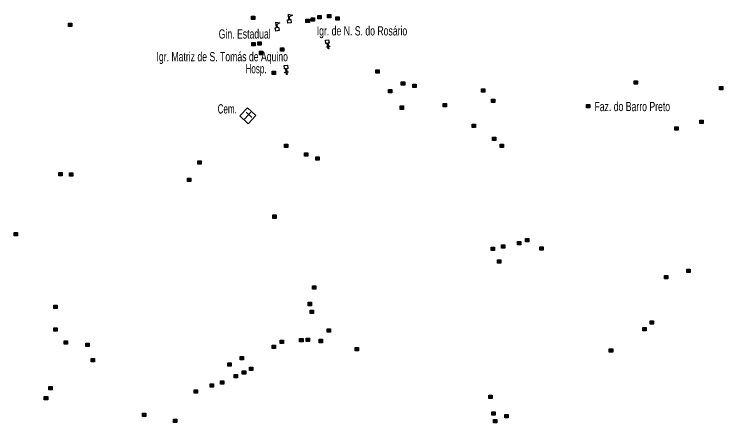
# Model space of a CAD drawing. Extents: x 265.7 to 292.1, y 7676.2 to 7704.2.
# Drawn here: x 279.25 to 285.37, y 7697.19 to 7700.73 of the extents above; entities that cross this region are included whole.
import ezdxf

# ---------------------------------------------------------------- set-up
doc = ezdxf.new("R2010")
doc.units = 0
doc.header["$LTSCALE"] = 0.032
doc.linetypes.add('MEDIUM_DASHED', pattern=[4.5, 3, -1.5])
for name, color, linetype, lineweight in [('2', 7, 'Continuous', 25), ('21', 7, 'MEDIUM_DASHED', 13), ('4', 7, 'Continuous', 25), ('6', 7, 'Continuous', 25)]:
    doc.layers.add(name, color=color, linetype=linetype, lineweight=lineweight)
doc.layers.add('61', color=7, linetype='Continuous')

msp = doc.modelspace()

# ---------------------------------------------------------------- hatches: boundary and pattern name
at = {"layer": '2'}
for points in [[(281.299, 7700.7082), (281.328, 7700.7082), (281.328, 7700.6792), (281.299, 7700.6792)], [(281.8735, 7700.7139), (281.9025, 7700.7139), (281.9025, 7700.6849), (281.8735, 7700.6849)], [(281.9558, 7700.722), (281.9848, 7700.722), (281.9848, 7700.693), (281.9558, 7700.693)], [(282.0282, 7700.7016), (282.0572, 7700.7016), (282.0572, 7700.6726), (282.0282, 7700.6726)], [(279.7179, 7700.6485), (279.7469, 7700.6485), (279.7469, 7700.6195), (279.7179, 7700.6195)], [(281.7709, 7700.6825), (281.7999, 7700.6825), (281.7999, 7700.6535), (281.7709, 7700.6535)], [(281.8163, 7700.6945), (281.8453, 7700.6945), (281.8453, 7700.6655), (281.8163, 7700.6655)], [(281.3014, 7700.4807), (281.3304, 7700.4807), (281.3304, 7700.4517), (281.3014, 7700.4517)], [(281.3553, 7700.4864), (281.3843, 7700.4864), (281.3843, 7700.4574), (281.3553, 7700.4574)], [(281.3699, 7700.4041), (281.3989, 7700.4041), (281.3989, 7700.3751), (281.3699, 7700.3751)], [(281.5506, 7700.4331), (281.5796, 7700.4331), (281.5796, 7700.4041), (281.5506, 7700.4041)], [(281.4796, 7700.2329), (281.5086, 7700.2329), (281.5086, 7700.2039), (281.4796, 7700.2039)], [(282.3738, 7700.2451), (282.4028, 7700.2451), (282.4028, 7700.2161), (282.3738, 7700.2161)], [(284.6086, 7700.1482), (284.6376, 7700.1482), (284.6376, 7700.1192), (284.6086, 7700.1192)], [(282.595, 7700.1418), (282.624, 7700.1418), (282.624, 7700.1128), (282.595, 7700.1128)], [(282.695, 7700.1207), (282.724, 7700.1207), (282.724, 7700.0917), (282.695, 7700.0917)], [(285.3454, 7700.1014), (285.3744, 7700.1014), (285.3744, 7700.0724), (285.3454, 7700.0724)], [(282.4829, 7700.074), (282.5119, 7700.074), (282.5119, 7700.045), (282.4829, 7700.045)], [(283.2875, 7700.0812), (283.3165, 7700.0812), (283.3165, 7700.0522), (283.2875, 7700.0522)], [(283.3746, 7699.99), (283.4036, 7699.99), (283.4036, 7699.961), (283.3746, 7699.961)], [(282.5837, 7699.9318), (282.6127, 7699.9318), (282.6127, 7699.9028), (282.5837, 7699.9028)], [(282.9558, 7699.9537), (282.9848, 7699.9537), (282.9848, 7699.9247), (282.9558, 7699.9247)], [(284.1945, 7699.9456), (284.2235, 7699.9456), (284.2235, 7699.9166), (284.1945, 7699.9166)], [(285.1767, 7699.8101), (285.2057, 7699.8101), (285.2057, 7699.7811), (285.1767, 7699.7811)], [(283.2075, 7699.7753), (283.2365, 7699.7753), (283.2365, 7699.7463), (283.2075, 7699.7463)], [(284.9581, 7699.7511), (284.9871, 7699.7511), (284.9871, 7699.7221), (284.9581, 7699.7221)], [(283.3826, 7699.6639), (283.4116, 7699.6639), (283.4116, 7699.6349), (283.3826, 7699.6349)], [(281.5862, 7699.6025), (281.6152, 7699.6025), (281.6152, 7699.5735), (281.5862, 7699.5735)], [(283.4504, 7699.6034), (283.4794, 7699.6034), (283.4794, 7699.5744), (283.4504, 7699.5744)], [(281.7589, 7699.5276), (281.7879, 7699.5276), (281.7879, 7699.4986), (281.7589, 7699.4986)], [(281.8558, 7699.4936), (281.8848, 7699.4936), (281.8848, 7699.4646), (281.8558, 7699.4646)], [(280.8347, 7699.459), (280.8637, 7699.459), (280.8637, 7699.43), (280.8347, 7699.43)], [(279.634, 7699.358), (279.663, 7699.358), (279.663, 7699.329), (279.634, 7699.329)], [(279.7275, 7699.3533), (279.7565, 7699.3533), (279.7565, 7699.3243), (279.7275, 7699.3243)], [(280.7468, 7699.3072), (280.7758, 7699.3072), (280.7758, 7699.2782), (280.7468, 7699.2782)], [(281.4829, 7698.9901), (281.5119, 7698.9901), (281.5119, 7698.9611), (281.4829, 7698.9611)], [(279.2482, 7698.8391), (279.2772, 7698.8391), (279.2772, 7698.8101), (279.2482, 7698.8101)], [(283.5989, 7698.76), (283.6279, 7698.76), (283.6279, 7698.731), (283.5989, 7698.731)], [(283.6692, 7698.7867), (283.6982, 7698.7867), (283.6982, 7698.7577), (283.6692, 7698.7577)], [(283.3721, 7698.7132), (283.4011, 7698.7132), (283.4011, 7698.6842), (283.3721, 7698.6842)], [(283.4617, 7698.7334), (283.4907, 7698.7334), (283.4907, 7698.7044), (283.4617, 7698.7044)], [(283.7911, 7698.7149), (283.8201, 7698.7149), (283.8201, 7698.6859), (283.7911, 7698.6859)], [(283.4263, 7698.6027), (283.4553, 7698.6027), (283.4553, 7698.5737), (283.4263, 7698.5737)], [(285.0621, 7698.5228), (285.0911, 7698.5228), (285.0911, 7698.4938), (285.0621, 7698.4938)], [(284.8701, 7698.4662), (284.8991, 7698.4662), (284.8991, 7698.4372), (284.8701, 7698.4372)], [(281.8259, 7698.3783), (281.8549, 7698.3783), (281.8549, 7698.3493), (281.8259, 7698.3493)], [(279.592, 7698.2097), (279.621, 7698.2097), (279.621, 7698.1807), (279.592, 7698.1807)], [(281.7904, 7698.2355), (281.8194, 7698.2355), (281.8194, 7698.2065), (281.7904, 7698.2065)], [(281.8073, 7698.1668), (281.8363, 7698.1668), (281.8363, 7698.1378), (281.8073, 7698.1378)], [(284.7466, 7698.0765), (284.7756, 7698.0765), (284.7756, 7698.0475), (284.7466, 7698.0475)], [(279.5913, 7698.0146), (279.6203, 7698.0146), (279.6203, 7697.9856), (279.5913, 7697.9856)], [(281.9549, 7698.0062), (281.9839, 7698.0062), (281.9839, 7697.9772), (281.9549, 7697.9772)], [(284.6828, 7698.0168), (284.7118, 7698.0168), (284.7118, 7697.9878), (284.6828, 7697.9878)], [(279.6799, 7697.9038), (279.7089, 7697.9038), (279.7089, 7697.8748), (279.6799, 7697.8748)], [(279.8679, 7697.8835), (279.8969, 7697.8835), (279.8969, 7697.8545), (279.8679, 7697.8545)], [(281.5482, 7697.9078), (281.5772, 7697.9078), (281.5772, 7697.8788), (281.5482, 7697.8788)], [(281.7161, 7697.9239), (281.7451, 7697.9239), (281.7451, 7697.8949), (281.7161, 7697.8949)], [(281.7725, 7697.9256), (281.8015, 7697.9256), (281.8015, 7697.8966), (281.7725, 7697.8966)], [(281.8856, 7697.9159), (281.9146, 7697.9159), (281.9146, 7697.8869), (281.8856, 7697.8869)], [(281.4772, 7697.8643), (281.5062, 7697.8643), (281.5062, 7697.8353), (281.4772, 7697.8353)], [(282.1955, 7697.8465), (282.2245, 7697.8465), (282.2245, 7697.8175), (282.1955, 7697.8175)], [(284.3931, 7697.8336), (284.4221, 7697.8336), (284.4221, 7697.8046), (284.3931, 7697.8046)], [(281.2021, 7697.7682), (281.2311, 7697.7682), (281.2311, 7697.7392), (281.2021, 7697.7392)], [(279.914, 7697.7496), (279.943, 7697.7496), (279.943, 7697.7206), (279.914, 7697.7206)], [(281.0947, 7697.7141), (281.1237, 7697.7141), (281.1237, 7697.6851), (281.0947, 7697.6851)], [(281.2206, 7697.6438), (281.2496, 7697.6438), (281.2496, 7697.6148), (281.2206, 7697.6148)], [(281.2827, 7697.6746), (281.3117, 7697.6746), (281.3117, 7697.6456), (281.2827, 7697.6456)], [(281.1488, 7697.6124), (281.1778, 7697.6124), (281.1778, 7697.5834), (281.1488, 7697.5834)], [(280.943, 7697.5317), (280.972, 7697.5317), (280.972, 7697.5027), (280.943, 7697.5027)], [(281.0317, 7697.556), (281.0607, 7697.556), (281.0607, 7697.527), (281.0317, 7697.527)], [(279.5475, 7697.5084), (279.5765, 7697.5084), (279.5765, 7697.4794), (279.5475, 7697.4794)], [(280.8041, 7697.4784), (280.8331, 7697.4784), (280.8331, 7697.4494), (280.8041, 7697.4494)], [(279.5088, 7697.4228), (279.5378, 7697.4228), (279.5378, 7697.3938), (279.5088, 7697.3938)], [(283.3519, 7697.4325), (283.3809, 7697.4325), (283.3809, 7697.4035), (283.3519, 7697.4035)], [(280.3586, 7697.2791), (280.3876, 7697.2791), (280.3876, 7697.2501), (280.3586, 7697.2501)], [(283.3786, 7697.2897), (283.4076, 7697.2897), (283.4076, 7697.2607), (283.3786, 7697.2607)], [(283.4908, 7697.2663), (283.5198, 7697.2663), (283.5198, 7697.2373), (283.4908, 7697.2373)], [(280.6267, 7697.225), (280.6557, 7697.225), (280.6557, 7697.196), (280.6267, 7697.196)], [(283.3908, 7697.2234), (283.4198, 7697.2234), (283.4198, 7697.1944), (283.3908, 7697.1944)]]:
    msp.add_hatch(color=256, dxfattribs=at).paths.add_polyline_path(points)

# ---------------------------------------------------------------- linework, layer by layer
for points in [[(281.299, 7700.7082), (281.328, 7700.7082), (281.328, 7700.6792), (281.299, 7700.6792)], [(281.8735, 7700.7139), (281.9025, 7700.7139), (281.9025, 7700.6849), (281.8735, 7700.6849)], [(281.9558, 7700.722), (281.9848, 7700.722), (281.9848, 7700.693), (281.9558, 7700.693)], [(282.0282, 7700.7016), (282.0572, 7700.7016), (282.0572, 7700.6726), (282.0282, 7700.6726)], [(279.7179, 7700.6485), (279.7469, 7700.6485), (279.7469, 7700.6195), (279.7179, 7700.6195)], [(281.7709, 7700.6825), (281.7999, 7700.6825), (281.7999, 7700.6535), (281.7709, 7700.6535)], [(281.8163, 7700.6945), (281.8453, 7700.6945), (281.8453, 7700.6655), (281.8163, 7700.6655)], [(281.3014, 7700.4807), (281.3304, 7700.4807), (281.3304, 7700.4517), (281.3014, 7700.4517)], [(281.3553, 7700.4864), (281.3843, 7700.4864), (281.3843, 7700.4574), (281.3553, 7700.4574)], [(281.3699, 7700.4041), (281.3989, 7700.4041), (281.3989, 7700.3751), (281.3699, 7700.3751)], [(281.5506, 7700.4331), (281.5796, 7700.4331), (281.5796, 7700.4041), (281.5506, 7700.4041)], [(281.4796, 7700.2329), (281.5086, 7700.2329), (281.5086, 7700.2039), (281.4796, 7700.2039)], [(282.3738, 7700.2451), (282.4028, 7700.2451), (282.4028, 7700.2161), (282.3738, 7700.2161)], [(284.6086, 7700.1482), (284.6376, 7700.1482), (284.6376, 7700.1192), (284.6086, 7700.1192)], [(282.595, 7700.1418), (282.624, 7700.1418), (282.624, 7700.1128), (282.595, 7700.1128)], [(282.695, 7700.1207), (282.724, 7700.1207), (282.724, 7700.0917), (282.695, 7700.0917)], [(285.3454, 7700.1014), (285.3744, 7700.1014), (285.3744, 7700.0724), (285.3454, 7700.0724)], [(282.4829, 7700.074), (282.5119, 7700.074), (282.5119, 7700.045), (282.4829, 7700.045)], [(283.2875, 7700.0812), (283.3165, 7700.0812), (283.3165, 7700.0522), (283.2875, 7700.0522)], [(283.3746, 7699.99), (283.4036, 7699.99), (283.4036, 7699.961), (283.3746, 7699.961)], [(282.5837, 7699.9318), (282.6127, 7699.9318), (282.6127, 7699.9028), (282.5837, 7699.9028)], [(282.9558, 7699.9537), (282.9848, 7699.9537), (282.9848, 7699.9247), (282.9558, 7699.9247)], [(284.1945, 7699.9456), (284.2235, 7699.9456), (284.2235, 7699.9166), (284.1945, 7699.9166)], [(285.1767, 7699.8101), (285.2057, 7699.8101), (285.2057, 7699.7811), (285.1767, 7699.7811)], [(283.2075, 7699.7753), (283.2365, 7699.7753), (283.2365, 7699.7463), (283.2075, 7699.7463)], [(284.9581, 7699.7511), (284.9871, 7699.7511), (284.9871, 7699.7221), (284.9581, 7699.7221)], [(283.3826, 7699.6639), (283.4116, 7699.6639), (283.4116, 7699.6349), (283.3826, 7699.6349)], [(281.5862, 7699.6025), (281.6152, 7699.6025), (281.6152, 7699.5735), (281.5862, 7699.5735)], [(283.4504, 7699.6034), (283.4794, 7699.6034), (283.4794, 7699.5744), (283.4504, 7699.5744)], [(281.7589, 7699.5276), (281.7879, 7699.5276), (281.7879, 7699.4986), (281.7589, 7699.4986)], [(281.8558, 7699.4936), (281.8848, 7699.4936), (281.8848, 7699.4646), (281.8558, 7699.4646)], [(280.8347, 7699.459), (280.8637, 7699.459), (280.8637, 7699.43), (280.8347, 7699.43)], [(279.634, 7699.358), (279.663, 7699.358), (279.663, 7699.329), (279.634, 7699.329)], [(279.7275, 7699.3533), (279.7565, 7699.3533), (279.7565, 7699.3243), (279.7275, 7699.3243)], [(280.7468, 7699.3072), (280.7758, 7699.3072), (280.7758, 7699.2782), (280.7468, 7699.2782)], [(281.4829, 7698.9901), (281.5119, 7698.9901), (281.5119, 7698.9611), (281.4829, 7698.9611)], [(279.2482, 7698.8391), (279.2772, 7698.8391), (279.2772, 7698.8101), (279.2482, 7698.8101)], [(283.5989, 7698.76), (283.6279, 7698.76), (283.6279, 7698.731), (283.5989, 7698.731)], [(283.6692, 7698.7867), (283.6982, 7698.7867), (283.6982, 7698.7577), (283.6692, 7698.7577)], [(283.3721, 7698.7132), (283.4011, 7698.7132), (283.4011, 7698.6842), (283.3721, 7698.6842)], [(283.4617, 7698.7334), (283.4907, 7698.7334), (283.4907, 7698.7044), (283.4617, 7698.7044)], [(283.7911, 7698.7149), (283.8201, 7698.7149), (283.8201, 7698.6859), (283.7911, 7698.6859)], [(283.4263, 7698.6027), (283.4553, 7698.6027), (283.4553, 7698.5737), (283.4263, 7698.5737)], [(285.0621, 7698.5228), (285.0911, 7698.5228), (285.0911, 7698.4938), (285.0621, 7698.4938)], [(284.8701, 7698.4662), (284.8991, 7698.4662), (284.8991, 7698.4372), (284.8701, 7698.4372)], [(281.8259, 7698.3783), (281.8549, 7698.3783), (281.8549, 7698.3493), (281.8259, 7698.3493)], [(279.592, 7698.2097), (279.621, 7698.2097), (279.621, 7698.1807), (279.592, 7698.1807)], [(281.7904, 7698.2355), (281.8194, 7698.2355), (281.8194, 7698.2065), (281.7904, 7698.2065)], [(281.8073, 7698.1668), (281.8363, 7698.1668), (281.8363, 7698.1378), (281.8073, 7698.1378)], [(284.7466, 7698.0765), (284.7756, 7698.0765), (284.7756, 7698.0475), (284.7466, 7698.0475)], [(279.5913, 7698.0146), (279.6203, 7698.0146), (279.6203, 7697.9856), (279.5913, 7697.9856)], [(281.9549, 7698.0062), (281.9839, 7698.0062), (281.9839, 7697.9772), (281.9549, 7697.9772)], [(284.6828, 7698.0168), (284.7118, 7698.0168), (284.7118, 7697.9878), (284.6828, 7697.9878)], [(279.6799, 7697.9038), (279.7089, 7697.9038), (279.7089, 7697.8748), (279.6799, 7697.8748)], [(279.8679, 7697.8835), (279.8969, 7697.8835), (279.8969, 7697.8545), (279.8679, 7697.8545)], [(281.5482, 7697.9078), (281.5772, 7697.9078), (281.5772, 7697.8788), (281.5482, 7697.8788)], [(281.7161, 7697.9239), (281.7451, 7697.9239), (281.7451, 7697.8949), (281.7161, 7697.8949)], [(281.7725, 7697.9256), (281.8015, 7697.9256), (281.8015, 7697.8966), (281.7725, 7697.8966)], [(281.8856, 7697.9159), (281.9146, 7697.9159), (281.9146, 7697.8869), (281.8856, 7697.8869)], [(281.4772, 7697.8643), (281.5062, 7697.8643), (281.5062, 7697.8353), (281.4772, 7697.8353)], [(282.1955, 7697.8465), (282.2245, 7697.8465), (282.2245, 7697.8175), (282.1955, 7697.8175)], [(284.3931, 7697.8336), (284.4221, 7697.8336), (284.4221, 7697.8046), (284.3931, 7697.8046)], [(281.2021, 7697.7682), (281.2311, 7697.7682), (281.2311, 7697.7392), (281.2021, 7697.7392)], [(279.914, 7697.7496), (279.943, 7697.7496), (279.943, 7697.7206), (279.914, 7697.7206)], [(281.0947, 7697.7141), (281.1237, 7697.7141), (281.1237, 7697.6851), (281.0947, 7697.6851)], [(281.2206, 7697.6438), (281.2496, 7697.6438), (281.2496, 7697.6148), (281.2206, 7697.6148)], [(281.2827, 7697.6746), (281.3117, 7697.6746), (281.3117, 7697.6456), (281.2827, 7697.6456)], [(281.1488, 7697.6124), (281.1778, 7697.6124), (281.1778, 7697.5834), (281.1488, 7697.5834)], [(280.943, 7697.5317), (280.972, 7697.5317), (280.972, 7697.5027), (280.943, 7697.5027)], [(281.0317, 7697.556), (281.0607, 7697.556), (281.0607, 7697.527), (281.0317, 7697.527)], [(279.5475, 7697.5084), (279.5765, 7697.5084), (279.5765, 7697.4794), (279.5475, 7697.4794)], [(280.8041, 7697.4784), (280.8331, 7697.4784), (280.8331, 7697.4494), (280.8041, 7697.4494)], [(279.5088, 7697.4228), (279.5378, 7697.4228), (279.5378, 7697.3938), (279.5088, 7697.3938)], [(283.3519, 7697.4325), (283.3809, 7697.4325), (283.3809, 7697.4035), (283.3519, 7697.4035)], [(280.3586, 7697.2791), (280.3876, 7697.2791), (280.3876, 7697.2501), (280.3586, 7697.2501)], [(283.3786, 7697.2897), (283.4076, 7697.2897), (283.4076, 7697.2607), (283.3786, 7697.2607)], [(283.4908, 7697.2663), (283.5198, 7697.2663), (283.5198, 7697.2373), (283.4908, 7697.2373)], [(280.6267, 7697.225), (280.6557, 7697.225), (280.6557, 7697.196), (280.6267, 7697.196)], [(283.3908, 7697.2234), (283.4198, 7697.2234), (283.4198, 7697.1944), (283.3908, 7697.1944)]]:
    msp.add_lwpolyline(points, close=True, dxfattribs=at)
at = {"layer": '21'}
for p, q in [((281.2942, 7699.8782), (281.2407, 7699.8194)), ((281.2526, 7699.8774), (281.3013, 7699.8325))]:
    msp.add_line(p, q, dxfattribs=at)
msp.add_lwpolyline([(281.2701, 7699.779), (281.3372, 7699.8488), (281.2664, 7699.9169), (281.1993, 7699.8471)], close=True, dxfattribs=at)
at = {"layer": '4'}
for points in [[(281.624, 7700.6769), (281.6203, 7700.7251), (281.655, 7700.7161), (281.6268, 7700.7032), (281.6288, 7700.6772)], [(281.517, 7700.6092), (281.5092, 7700.6569), (281.5445, 7700.6509), (281.5176, 7700.6357), (281.5218, 7700.6099)], [(281.6288, 7700.6772), (281.6409, 7700.678), (281.6429, 7700.6492), (281.6141, 7700.6471), (281.6119, 7700.676), (281.624, 7700.6769)], [(281.5218, 7700.6099), (281.5338, 7700.6118), (281.5383, 7700.5832), (281.5097, 7700.5787), (281.5051, 7700.6073), (281.517, 7700.6092)]]:
    msp.add_lwpolyline(points, dxfattribs=at)
at = {"layer": '6'}
for points in [[(281.955, 7700.4732), (281.943, 7700.4712), (281.9382, 7700.4997), (281.9668, 7700.5046), (281.9716, 7700.476), (281.9597, 7700.474)], [(281.9597, 7700.474), (281.9643, 7700.4473), (281.9762, 7700.4493), (281.977, 7700.4445), (281.9651, 7700.4425), (281.9678, 7700.4263), (281.9631, 7700.4255), (281.9604, 7700.4416), (281.9484, 7700.4396), (281.9476, 7700.4444), (281.9595, 7700.4465), (281.955, 7700.4732)], [(281.5968, 7700.2527), (281.5848, 7700.2515), (281.5817, 7700.2803), (281.6105, 7700.2834), (281.6136, 7700.2545), (281.6016, 7700.2533)], [(281.6016, 7700.2533), (281.6045, 7700.2263), (281.6165, 7700.2276), (281.617, 7700.2227), (281.605, 7700.2214), (281.6068, 7700.2051), (281.602, 7700.2046), (281.6002, 7700.2209), (281.5882, 7700.2196), (281.5877, 7700.2245), (281.5997, 7700.2258), (281.5968, 7700.2527)]]:
    msp.add_lwpolyline(points, dxfattribs=at)

# ---------------------------------------------------------------- texts
at = {"layer": '61'}
for s, width, p in [('Gin. Estadual', 0.7, (281.0163, 7700.5143)), ('Igr. de N. S. do Rosário', 0.7, (281.8638, 7700.5413)), ('Igr. Matriz de S. Tomás de Aquino', 0.7, (280.4787, 7700.3181)), ('Hosp.', 0.65, (281.2486, 7700.2144)), ('Faz. do Barro Preto', 0.7, (284.2649, 7699.8873)), ('Cem.', 0.65, (281.007, 7699.8671))]:
    msp.add_text(s, height=0.08, dxfattribs=dict(at, width=width)).set_placement(p)

doc.saveas('drawing.dxf')
